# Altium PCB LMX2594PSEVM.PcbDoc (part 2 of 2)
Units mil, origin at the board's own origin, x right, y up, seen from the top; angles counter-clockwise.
Board outline 1260 x 3135 mil, 4 copper layers (Top Layer, GND, Power, Bottom Layer), stack 61.6 mil thick; 123 components, 80 nets, 426 pads, 190 vias.
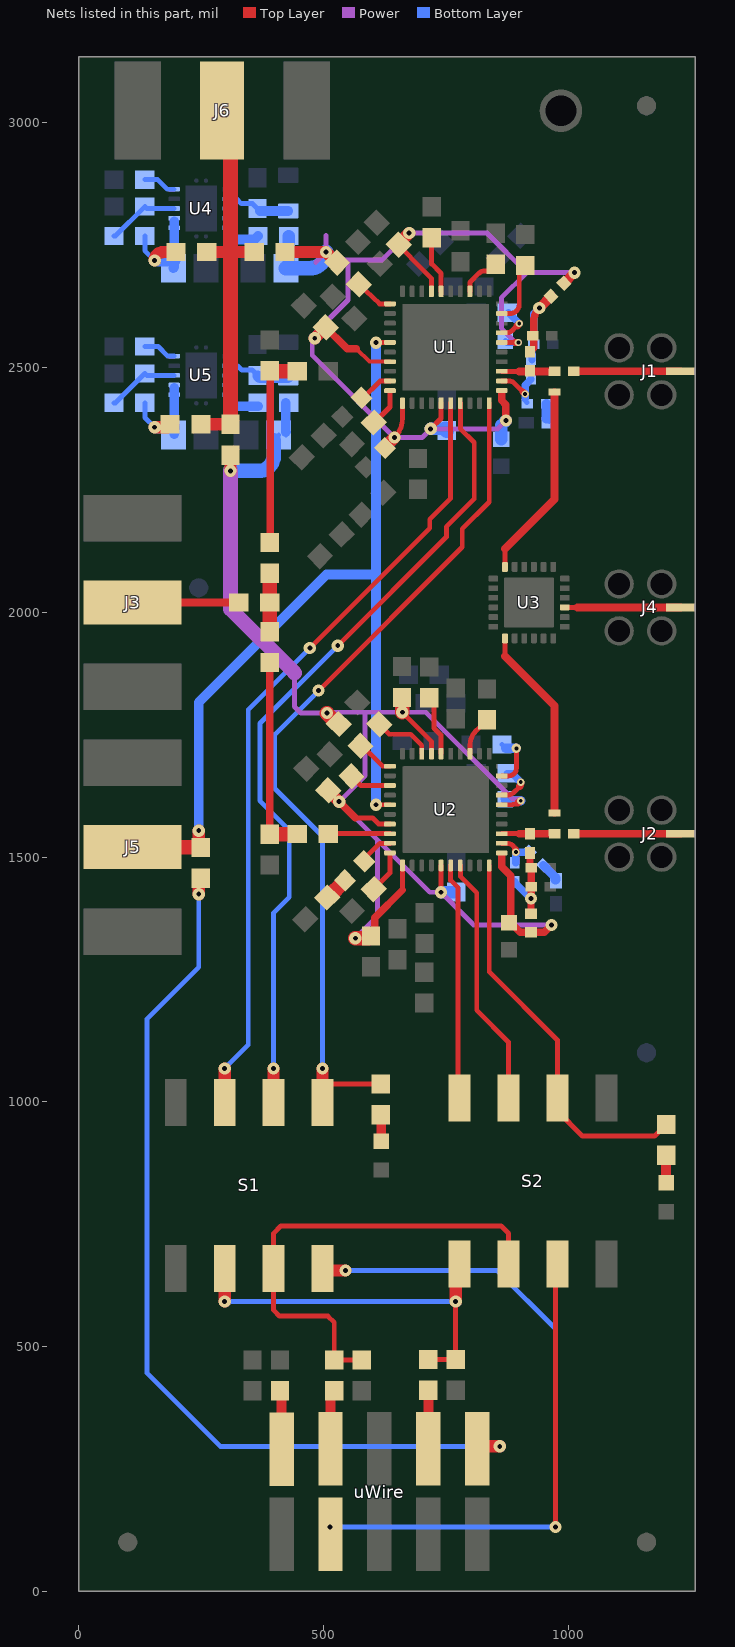
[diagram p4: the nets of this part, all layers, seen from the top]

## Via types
v1: diameter 25, hole 10, Top Layer to Bottom Layer, tented both sides, 120 vias
v2: diameter 19.68, hole 7.87, Top Layer to Bottom Layer, tented bottom, 29 vias
v3: diameter 28, hole 16, Top Layer to Bottom Layer, tented both sides, 18 vias
v4: diameter 15, hole 8, Top Layer to Bottom Layer, tented both sides, 14 vias
v5: diameter 19.68, hole 7.87, Top Layer to Bottom Layer, tented top, 8 vias
v6: diameter 20, hole 8, Top Layer to Bottom Layer, tented both sides, 1 vias

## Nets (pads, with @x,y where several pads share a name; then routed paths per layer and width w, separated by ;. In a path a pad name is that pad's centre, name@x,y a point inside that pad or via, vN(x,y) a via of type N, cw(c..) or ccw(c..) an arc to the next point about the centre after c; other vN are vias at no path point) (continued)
NetC10_2: C10.2 U1.9 | length 71.8
  Top Layer w10: C10.2@579.15,2436.17 615.64,2472.67 U1.9@635.86,2472.67
NetC11_2: C11.2 U1.10 | length 86.3
  Top Layer w10: C11.2@598.14,2381.86 635.86,2419.57 U1.10@635.86,2452.57
NetC13_1: C13.1 C13p.1 R21.2 U1.23 | length 103.6
  Top Layer w10: U1.23@864.17,2492.35 899.81,2492.35
  Top Layer w16: 900,2492.34 C13.1@968,2492.34
NetC13_2: C13.2 J1.1 | length 218.3
  Top Layer w16: C13.2@1011.69,2492.36 J1.1@1230,2492.36
NetC14_2: C14.2 C15.2 L1.1 R21.1 R22.2 | length 242.8
  Top Layer w15: R21.1@922,2532.54 929.31,2539.86 929.31,2562 929.31,2593.79 cw(c969.21,2593.79) v1(941,2622)
  Top Layer w20: v1(941,2622) L1.1@964.78,2645.78
  Bottom Layer w10: C15.2@924,2539.69 C15.2@929.31,2545
  Bottom Layer w15: R22.2@926,2515.79 C15.2@926,2540 ; C15.2@929.31,2545 929.31,2610.31 v1(941,2622)
NetC16_1: C16.1 U1.29 | length 131.2
  Top Layer w10: U1.29@864.17,2610.47 881.47,2610.47 ccw(c881.47,2629) 900,2629 900,2696.71 C16.1@912.05,2708.76
NetC17_1: C17.1 U1.33 | length 114.9
  Top Layer w10: U1.33@799.21,2655.74 799.21,2674.21 818.46,2693.46 cw(c827,2684.93) 827,2697 C17.1@837.64,2697 ; C17.1@837.64,2697 852,2697 C17.1@852,2711.36 C17.1@837.64,2697
NetC18_1: C18.1 U1.36 | length 117.6
  Top Layer w10: C18.1@721,2765.36 721,2712 740.16,2692.84 U1.36@740.16,2655.74
NetC20_1: C20.1 U2.38 | length 119.2
  Top Layer w10: C20.1@615.76,1769.17 634.07,1750.86 678.14,1750.86 700.79,1728.21 U2.38@700.79,1711.03
NetC21_2: C21.2 U2.3 | length 86.5
  Top Layer w10: C21.2@557.27,1665.17 576.37,1646.07 U2.3@635.83,1646.07
NetC23_2: C23.2 U2.8 | length 126.6
  Top Layer w10: C23.2@509.5,1547 510.14,1547.65 U2.8@635.83,1547.65
NetC24_1: C24.1 R16.2 | length 51.3
  Top Layer w10: R16.2@507.27,1417.27 R16.2@509.14,1417.27
  Top Layer w30: R16.2@509.14,1417.27 C24.1@544.12,1452.25
NetC24_2: C24.2 U2.9 | length 80.9
  Top Layer w10: C24.2@583.09,1491.22 583.09,1496.09 614.96,1527.96 U2.9@635.83,1527.96 635.72,1527.86 U2.9@625.73,1527.86
NetC25_2: C25.2 U2.10 | length 86.9
  Top Layer w10: C25.2@602.68,1434.34 635.83,1467.48 U2.10@635.83,1507.48
NetC28_2: C28.2 C29.2 L2.1 R17.1 R24.2 | length 178
  Top Layer w10: C29.2@922,1479.31 C29.2@924.31,1477
  Top Layer w15: C29.2@922,1479.31 R17.1@922,1508.17 ; L2.1@924,1383.7 v1(924,1415) ; v1@924.31,1410.31 924.31,1440 C29.2@924.31,1477
  Bottom Layer w15: R24.2@891,1449.24 891,1448 v1(924,1415)
NetC30_1: C30.1 J2.1 | length 218.3
  Top Layer w16: C30.1@1011.68,1547.65 J2.1@1230,1547.65
NetC30_2: C30.2 C30p.2 R17.2 U2.23 | length 99.9
  Top Layer w10: U2.23@864.17,1547.65 896.1,1547.65
  Top Layer w16: 900,1547.65 C30p.2@968,1547.65
NetC31_2: C31.2 U2.33 | length 82
  Top Layer w10: U2.33@799.21,1711.03 799.21,1728 cw(c841.98,1728) 811.74,1758.24 C31.2@834,1780.5
NetC32_2: C32.2 U2.36 | length 108.9
  Top Layer w10: C32.2@725.56,1813.86 725.56,1763.6 740.16,1749 U2.36@740.16,1711.03
NetC34_2: C34.2 U1.27 | length 82.7
  Top Layer w10: U1.27@864.17,2571.1 872.74,2571.1 ccw(c872.74,2591.26) 887,2577 v4(900,2590)
  Top Layer w15: v4@895.76,2585.76 v4(900,2590)
  Bottom Layer w10: C34.2@875.2,2612 C34.2@878,2612
  Bottom Layer w15: C34.2@878,2612 v4(900,2590)
NetC38_1: C38.1 U2.29 | length 107
  Top Layer w8: U2.29@864.17,1665.76 U2.29@864.28,1665.86
  Top Layer w10: U2.29@864.28,1665.86 878.45,1665.86 ccw(c878.45,1681.41) 894,1681.41 v6@894,1716.86
  Bottom Layer w10: C38.1@864.5,1730 C38.1@872.5,1722
  Bottom Layer w20: C38.1@872.5,1722 v6(894,1722)
NetC39_2: C39.2 U2.27 | length 84.4
  Top Layer w10: U2.27@864.17,1626.39 874.28,1626.39 ccw(c874.28,1648.63) 890,1632.9 897.98,1640.88 ; v4@903,1651.24 v4(903,1653)
  Top Layer w15: 900.7,1644.43 ccw(c885.85,1653) v4(903,1653)
  Bottom Layer w15: C39.2@875.2,1670 886,1670 v4(903,1653)
NetC42_1: C42.1 R25.1 | length 40
  Bottom Layer w18: C42.1@948.92,1483.08 R25.1@974.3,1457.7
  Bottom Layer w20: R25.1@974.3,1453.62 R25.1@974.3,1457.7
NetC42_2: C42.2 R24.1 U2.22 | length 93.9
  Top Layer w10: U2.22@864.17,1527.96 874.9,1527.96 cw(c874.9,1509.86) v4(893,1509.86)
  Top Layer w15: v4@892.38,1514.54 cw(c874.9,1509.86) v4(893,1509.86)
  Bottom Layer w15: R24.1@893,1488.37 v4(893,1509.86) 920.02,1509.86 C42.2@921.08,1510.92
NetC43_1: C43.1 R23.1 | length 37.8
  Bottom Layer w10: R23.1@955.68,2395.54 R23.1@961.23,2390
  Bottom Layer w20: R23.1@955.68,2395.54 C43.1@955.68,2425.54
NetC43_2: C43.2 R22.1 U1.22 | length 117.8
  Top Layer w10: U1.22@864.17,2472.67 878.84,2472.67 cw(c878.84,2457.01) 889.92,2468.08 v4(912,2446)
  Top Layer w15: v4@907.76,2450.24 v4(912,2446)
  Bottom Layer w10: 912,2436.62 ccw(c923.67,2436.62) C43.2@915.42,2428.37
  Bottom Layer w15: 912,2436.62 v4(912,2446) 912,2464.1 R22.1@924,2476.1
NetC44_2: C44.2 R29.2 U4.7 | length 133.1
  Bottom Layer w10: U4.7@305.12,2844.69 322.32,2844.69 332,2835 355,2835 R29.2@365,2825 R29.2@370,2820
  Bottom Layer w20: R29.2@370,2820 C44.2@428,2820
NetC45_2: C45.2 R34.2 U5.7 | length 133.9
  Bottom Layer w10: U5.7@305.12,2503.69 324.32,2503.69 333,2495 354,2495 R34.2@365,2484
  Bottom Layer w20: R34.2@365,2484 ccw(c370,2484) 370,2479 C45.2@428,2479
NetD1_1: D1.1 R12.1 | length 35.6
  Top Layer w20: D1.1@618,922.77 R12.1@618,958.36
NetD2_1: D2.1 R13.1 | length 56
  Top Layer w20: D2.1@1200,834.39 R13.1@1200,890.36
NetJ3_1: J3.1 R3.1 | length 216
  Top Layer w16: J3.1@111,2020 R3.1@327.01,2020
NetJ4_1: J4.1 U3.3 | length 235.1
  Top Layer w10: U3.3@994.8,2009.92 1018.93,2009.92
  Top Layer w16: 1019,2009.92 J4.1@1230,2009.92
NetJ6_1: J6.1 R1.1 R2.1 R37.1 R38.1 | length 908.9
  Top Layer w25: R2.1@249.5,2384 R38.1@310,2384 ; R1.1@261.5,2736 301,2736 ; 319,2736 ccw(c319,2727) 310,2727 ccw(c301,2727) 301,2736 ; R37.1@358.5,2736 310,2736 301,2736
  Top Layer w30: J6.1@293,2959.87 J6.1@293,3025 310,3025 310,2736 310,2727 R38.1@310,2384
NetR3_2: R3.2 R4.1 R5.2 | length 119
  Top Layer w30: R5.2@390,1960.5 R3.2@390,2020 R4.1@390,2079.5
NetR7_1: R7.1 uWire.2 | length 119.7
  Top Layer w20: R7.1@411,408.36 414.27,405.09 uWire.2@414.27,290.01
NetR8_2: R8.2 uWire.4 | length 122.6
  Top Layer w10: R8.2@514.27,402.63 R8.2@522,410.36
  Top Layer w20: uWire.4@514.27,291.01 R8.2@514.27,402.63
NetR10_1: R10.1 uWire.8 | length 115.1
  Top Layer w20: uWire.8@714.27,291.01 R10.1@714.27,406.09
NetR14_2: R14.2 U2.1 | length 79.8
  Top Layer w10: R14.2@574.83,1730.86 575.23,1730.86 620.64,1685.44 U2.1@635.83,1685.44
NetR18_2: R18.2 U1.1 | length 79.5
  Top Layer w10: R18.2@572.08,2670.02 614.71,2630.15 U1.1@635.86,2630.15
NetR26_2: R26.2 uWire.10 | length 1893.9
  Top Layer w10: R26.2@245,1452.5 R26.2@249,1456.5 ; uWire.10@814.27,291.01 uWire.10@819.11,295.86
  Top Layer w25: v1(245,1424) R26.2@245,1452.5 ; uWire.10@819.11,295.86 v1(860,295.86)
  Bottom Layer w10: v1@243.93,1428.79 242,1426.86 v1@245,1423.86 ; 245,1274.86 139,1168.86 139,445.86 289,295.86 v1(860,295.86) ; 245,1275 v1@245,1423.86 ; v1(245,1424) v1@245,1423.86
NetR27_1: R27.1 R28.2 U4.3 | length 149.4
  Bottom Layer w10: R27.1@72.01,2769 75,2769 R28.2@135,2829 139,2825 U4.3@194.88,2825
NetR30_1: R30.1 U4.8 U4.9 U4.10 | length 113.1
  Bottom Layer w10: 305,2777.86 305.12,2777.74 ; U4.9@305.12,2805.32 U4.8@305.12,2824
  Bottom Layer w20: 305,2777.86 ccw(c320.86,2777.86) 320.86,2762 359,2762 R30.1@366,2769 ; 305.12,2777.74 U4.10@305.12,2785.63 305.12,2799
NetR31_2: R31.2 U4.5 | length 68
  Bottom Layer w10: R31.2@135,2884 161,2884 180.63,2864.37 U4.5@194.88,2864.37
NetR32_1: R32.1 R33.2 U5.3 | length 149.4
  Bottom Layer w10: R32.1@72.01,2428 75,2428 R33.2@135,2488 139,2484 U5.3@194.88,2484
NetR35_1: R35.1 U5.8 U5.9 U5.10 | length 110.8
  Bottom Layer w10: U5.9@305.12,2464.31 U5.8@305.12,2483
  Bottom Layer w20: 305.12,2459 U5.10@305.12,2444.63 305.12,2436.74 ccw(c320.86,2436.74) 320.86,2421 R35.1@366,2421
NetR36_2: R36.2 U5.5 | length 68
  Bottom Layer w10: R36.2@135,2543 162,2543 181.63,2523.37 U5.5@194.88,2523.37
OSCIN_U1: C9.1 R4.2 R19.2 | length 407
  Top Layer w10: R19.2@391,2493.5 R19.2@392.15,2492.35
  Top Layer w16: R4.2@391,2142.5 R19.2@391,2493.5
  Top Layer w30: R19.2@392.15,2492.35 C9.1@446.5,2492.35
OSCIN_U2: C23.1 R5.1 R15.2 | length 410
  Top Layer w10: C23.1@446,1546.5 C23.1@446.5,1547
  Top Layer w16: R15.2@390,1546.5 R5.1@390,1897.5
  Top Layer w22: C23.1@445.85,1546.05 C23.1@447.44,1547.65
  Top Layer w30: R15.2@390,1546.5 C23.1@446,1546.5
READBACK: S1.4 S2.3 uWire.3 | length 1932.3
  Top Layer w10: S1.4@498,659.57 S1.4@502.57,655 ; v1@974.27,131.13 974.27,664.84 S2.3@978,668.57
  Top Layer w25: S1.4@502.57,655 v1(545,655)
  Bottom Layer w10: v1(513,130.86) 628.25,130.86 858.75,130.86 v1(974,130.86) 974,536 855,655 v1(545,655)
READBACK_U1: R12.2 S1.5 U1.20 | length 1793.8
  Top Layer w10: v1(490,1840) 783.5,2133.5 ; S1.5@496,998.15 498,1000.15 S1.5@498,998.15 498,1036.35 R12.2@617,1036.35 ; 783.5,2152 783.5,2133.5 ; U1.20@838.58,2427.39 838.58,2225.44 783.5,2170.36 783.5,2133.5
  Top Layer w25: S1.5@498,1036.35 v1(498,1068)
  Bottom Layer w10: v1(490,1840) 400,1750 400,1640 498,1542 v1(498,1068)
READBACK_U2: R13.2 S2.6 U2.20 | length 812.2
  Top Layer w10: U2.20@838.58,1482.69 838.58,1265.28 978,1125.86 S2.6@978,1007.15 978,981 1029,930 1176.65,930 R13.2@1200,953.35
RFout1: C13p.2 U3.12 | length 398.1
  Top Layer w10: U3.12@870.79,2092.8 870.79,2129.79
  Top Layer w16: 870.79,2129.79 972,2231 C13p.2@972,2449
RFout2: C30p.1 U3.19 | length 397.7
  Top Layer w10: 870.79,1910.21 U3.19@870.79,1946.74
  Top Layer w16: 870.79,1910.21 972,1809 C30p.1@972,1591
SCK: R10.2 R11.2 S1.2 S2.1 | length 794.1
  Top Layer w10: R10.2@714,473.35 R11.2@770,473.35 v1(770,592) ; S2.1@770,660.57 S2.1@778,668.57
  Top Layer w25: v1(298,592) S1.2@298,659.57 ; v1(770,592) S2.1@770,660.57
  Bottom Layer w10: v1(298,592) v1(770,592)
SCK_U1: S1.7 U1.16 | length 1621.5
  Top Layer w10: v1@472,1925.86 v1(472,1926.86) 717,2171.86 717,2189.86 759.84,2232.7 U1.16@759.84,2427.39
  Top Layer w25: S1.7@298,998.15 v1(298,1068)
  Bottom Layer w10: v1(298,1068) 346.14,1116.14 346.14,1801 v1(472,1926.86)
SCK_U2: S2.8 U2.16 | length 440.8
  Top Layer w10: U2.16@759.84,1482.69 759.84,1452.16 775,1437 S2.8@775,1048.15
SDI: R8.1 R9.2 S1.3 S2.2 | length 983.1
  Top Layer w10: S1.3@401,662.57 S1.3@398,659.57 ; R9.2@578,472.35 R8.1@522,472.35 522,549 509,562 410,562 398,574 S1.3@398,659.57 ; S2.2@878,668.57 878,731 863,746 413,746 398,731 S1.3@398,659.57
SDI_U1: S1.6 U1.17 | length 1660.6
  Top Layer w10: v1(529,1931.86) 751,2153.86 751,2174.86 808,2231.86 808,2346.86 779.53,2375.33 U1.17@779.53,2427.39
  Top Layer w25: S1.6@398,998.15 v1(398,1068)
  Bottom Layer w10: v1(398,1068) 398,1385.86 430,1417.86 430,1554.86 370,1614.86 370,1772.86 v1(529,1931.86)
SDI_U2: S2.7 U2.17 | length 527.7
  Top Layer w10: S2.7@878,1007.15 878,1121.86 813,1186.86 813,1427 779.53,1460.47 U2.17@779.53,1471.33 ; U2.17@779.53,1471.33 U2.17@779.53,1482.69 U2.17@779.53,1471.33
SYNC: J5.1 R26.1 U1.5 U2.5 | length 1915.5
  Top Layer w10: v1(607.16,1606.7) U2.5@635.83,1606.7 ; v1@607.55,2551.41 U1.5@635.86,2551.41
  Top Layer w25: R26.1@245,1520.5 v1(245,1553.86)
  Top Layer w30: J5.1@103,1519.86 R26.1@246,1520 ; R26.1@243.93,1519.35 R26.1@245,1520.42
  Bottom Layer w20: v1(245,1553.86) 245,1816.07 505.93,2077 ; 510,2077 505.93,2077 ; v1(607.16,1606.7) v1@607.16,2550.86 ; 607.16,2077 505.93,2077
  other v1: 607,2550.86
VCC1: C2.2 C5.1 C8.2 C12.2 C35.1 C36.2 C37.1 L1.2 R18.1 R30.2 R37.2 U1.7 U1.11 U1.15 U1.21 U1.26 U1.37 | length 2571.2
  Top Layer w8: 567.5,2538.36 593.82,2512.04 U1.7@635.86,2512.04
  Top Layer w10: C8.2@499.46,2577.46 C8.2@499.46,2587.09 ; R18.1@526.44,2714.56 R18.1@527.54,2714.56 ; v1@644.77,2357 v1(645,2357) ccw(c605.29,2396.71) 661.45,2396.71 ; v1@645,2357.23 v1@645,2358 ; C5.1@653.39,2751.3 653.39,2749.61 703.13,2699.87 703.13,2699.75 720.5,2682.38 U1.37@720.47,2655.74 ; 661.45,2405 661.45,2396.71 ; U1.11@661.42,2427.39 661.45,2396.71 ; v1@722.37,2374.86 v1(719,2374.86) 740.16,2396.02 U1.15@740.16,2427.39 ; U1.26@864.17,2551.41 v4(898,2551.41)
  Top Layer w15: C8.2@499.46,2587.09 548.2,2538.36 567.5,2538.36 ; U1.21@864.2,2448.86 864.2,2432.86 872.69,2424.37 v1(872.69,2391.9) ; v4@892,2551.41 v4(898,2551.41)
  Top Layer w20: L1.2@991.22,2672.22 v1(1013,2694)
  Top Layer w25: R37.2@421.5,2736 v1(505,2736) R18.1@526.44,2714.56 ; v1(482,2560) C8.2@499.46,2577.46 ; C12.2@624.64,2336.87 v1@644.77,2357 ; C5.1@653.39,2751.3 653.39,2753.39 v1(675,2775)
  Power w10: 484.14,2715 v1@505,2735.86 ; 505,2769.86 v1(505,2736) v1@505,2735.86 ; v1(872.69,2391.9) 855.64,2374.86 v1(719,2374.86) 701.14,2357 v1(645,2357) 477,2525 477,2565 550,2638 550,2720 ; v4@893,2550.86 863.43,2580.43 863.43,2642.43 915,2694 ; v1(1013,2694) 915,2694 ; v1@505,2735.86 520.86,2720 550,2720 ; 550,2720 620,2720 v1(675,2775) 834,2775 915,2694
  Bottom Layer w10: C2.2@423,2703 C2.2@428.99,2708.99 ; C35.1@871.56,2555 C35.1@875.15,2551.41
  Bottom Layer w15: C35.1@875.15,2551.41 v4(898,2551.41)
  Bottom Layer w25: C2.2@428.99,2708.99 R30.2@428.99,2769 ; v1(719,2374.86) C36.2@748.5,2374.86 ; C37.1@863,2353.56 863,2382.21 v1(872.69,2391.9)
  Bottom Layer w30: C2.2@423,2703 472,2703 ccw(c472,2736) v1(505,2736) ; C36.2@748.5,2374.86 C36.2@752,2371.36
VCC2: C4.2 C22.2 C26.2 C27.1 C33.1 C40.1 C41.2 L2.2 R14.1 R35.2 R38.2 U2.7 U2.11 U2.15 U2.21 U2.26 U2.37 | length 3248.1
  Top Layer w5: C26.2@592.5,1334 C26.2@597,1338.5 C26.2@594.5,1336 ; C27.1@882.29,1365.81 C27.1@887.79,1365.81
  Top Layer w10: R14.1@529.33,1771.67 R14.1@531.02,1771.67 ; v1(532,1613) v1@532,1613.62 ; 565.14,1579.86 600,1579.86 612.53,1567.33 U2.7@635.83,1567.33 ; C26.2@592.5,1334 C26.2@594.5,1336 ; C26.2@597,1338.5 C26.2@605,1346.5 ; v1(661,1795.86) 720.47,1736.39 U2.37@720.47,1711.03 ; 661.42,1432.42 U2.11@661.42,1482.69 ; v1(740,1428) 740.16,1428.16 U2.15@740.16,1482.69 ; U2.26@864.17,1606.7 882.96,1606.7 ccw(c882.96,1635.04) v4(903,1615)
  Top Layer w15: v1(532,1613) 565.14,1579.86 ; C26.2@605,1346.5 605,1376 661.42,1432.42 ; U2.21@864.17,1504 864.17,1480 882.29,1461.89 882.29,1365.81 901.8,1346.3 L2.2@924,1346.3 950.84,1346.3 v1(965.7,1361.16) ; v4@897.13,1610.5 ccw(c882.96,1635.04) v4(903,1615)
  Top Layer w25: v1(310,2289) R38.2@310,2321.01 ; C22.2@509.51,1635.49 v1(532,1613)
  Top Layer w30: v1(507,1794) R14.1@529.33,1771.67 ; v1(565,1334) C26.2@592.5,1334 ; v1(661,1795.86) C33.1@661,1825.26
  Power w10: 440.78,1876.08 440.78,1807.22 454,1794 v1(507,1794) 508.86,1795.86 584.93,1795.86 ; v1(565,1334) 610,1379 610,1535 ; v4@903,1618.86 886.14,1618.86 709.14,1795.86 v1(661,1795.86) 584.93,1795.86 ; v1(965.7,1361.16) 806.84,1361.16 v1(740,1428) 717,1428 610,1535 ; 584.93,1795.86 584.93,1665.93 v1(532,1613) 610,1535
  Power w30: v1(310,2289) 310,2006 440.78,1876.08
  Bottom Layer w10: C4.2@398,2351.54 C4.2@408.46,2362 ; C4.2@423,2362 C4.2@428.99,2367.99 ; C41.2@766.5,1428 C41.2@771,1423.5
  Bottom Layer w20: C4.2@423,2367.99 R35.2@423,2428 ; C40.1@871.96,1619.72 C40.1@872.82,1618.86 ; C40.1@872.82,1615 v4(903,1615)
  Bottom Layer w25: v1(740,1428) C41.2@766.5,1428
  Bottom Layer w30: v1(310,2289) 368,2289 ccw(c368,2319) 398,2319 C4.2@398,2351.54
Vin1: C1.2 R1.2 R27.2 U4.1 U4.2 | length 248.3
  Top Layer w25: v1(155,2719) cw(c172,2719) 172,2736 R1.2@198.5,2736
  Bottom Layer w10: R27.2@135,2769 135,2739 v1(155,2719) ; 194.88,2777.74 195,2777.86
  Bottom Layer w20: C1.2@193.07,2703 194.88,2704.81 194.88,2719 194.88,2777.74 U4.1@194.88,2785.63 194.88,2799
  Bottom Layer w25: v1(155,2719) C1.2@194.88,2719
Vin2: C3.2 R2.2 R32.2 U5.1 U5.2 | length 230.3
  Top Layer w10: R2.2@180.5,2378 R2.2@186.5,2384
  Top Layer w25: v1(155,2378) R2.2@180.5,2378
  Bottom Layer w10: R32.2@135,2428 135,2398 v1(155,2378) ; C3.2@193.07,2362 C3.2@194.88,2363.81 ; C3.2@193.88,2378 C3.2@194.88,2379
  Bottom Layer w20: C3.2@194.88,2363.81 194.88,2379 U5.1@194.88,2444.63 194.88,2459
  Bottom Layer w25: v1(155,2378) C3.2@193.88,2378
pads on no net: FID1.1 FID2.1 FID3.1 FID4.1 FID5.1 FID6.1 U1.18 U1.19 U1.28 U1.30 U1.32 U1.41@692.52,2484.09 U1.41@692.52,2541.57 U1.41@692.52,2599.05 U1.41@750,2484.09 U1.41@750,2541.57 U1.41@750,2599.05 U1.41@807.48,2484.09 U1.41@807.48,2541.57 U1.41@807.48,2599.05 U2.18 U2.19 U2.28 U2.30 U2.32 U2.41@692.52,1539.38 U2.41@692.52,1596.86 U2.41@692.52,1654.34 U2.41@750,1539.38 U2.41@750,1596.86 U2.41@750,1654.34 U2.41@807.48,1539.38 U2.41@807.48,1596.86 U2.41@807.48,1654.34 U3. U4.4 U5.4 uWire.1 uWire.5 uWire.7 uWire.9

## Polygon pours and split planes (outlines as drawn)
GND on GND "GND_L02_P012" (solid, remove dead copper, pour order 12): 1260,0 1260,3135 0,3135 0,0
GND on Power "GND_L03_P036" (solid, remove dead copper, pour order 36): 0,2330 550,2330 550,3135 0,3135
VCC2 on Power "VCC2_L03_P034" (solid, remove dead copper, pour order 34): 415,1320 980,1320 980,1555 640,1895 415,1895
VCC1 on Power "VCC1_L03_P032" (solid, remove dead copper, pour order 32): 1050,2890 460,2890 460,2330 955,2330 955,2655 1050,2655
GND on Top Layer "GND_L01_P030" (solid, remove dead copper, pour order 30): 1260,1385 865,1385 865,1820 815,1820 815,2480 900,2480 900,2655 1260,2655

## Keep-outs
Keep-Out Layer:
  text ".Layer_Name" at -520,-895 h60

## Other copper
Top Layer:
  text ".Layer_Name" at -520,-895 h60
Power:
  text ".Layer_Name" at -520,-895 h60
GND:
  text ".Layer_Name" at -520,-895 h60
Bottom Layer:
  rectangle net GND: 659,2451.86 841,2630.86
  rectangle net GND: 660,1505.86 841,1686.86
  pour cut-out: 350,2730
  text ".Layer_Name" at -520,-895 h60

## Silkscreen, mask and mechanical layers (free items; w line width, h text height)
Top Overlay:
  lines w5: 490,2390 510,2410 ; 904,1519 904,1458 ; 904,1571 904,1576 940,1576 940,1571 ; 905,2470 905,2465 939,2465 939,2470 ; 905,2522 905,2543 ; 908,2553 908,2584 925,2584 ; 909,1458 904,1458 ; 924,1421 904,1421 904,1458 ; 939,2522 939,2543 ; 940,1497 940,1519 ; 944,1587 944,1607 949,1607 ; 944,2450 944,2430 949,2430 ; 956,1524 956,1519 1025,1519 1025,1524 ; 956,2515 956,2520 1025,2520 1025,2515 ; 959,1421 984,1421 984,1459 ; 959,1496 984,1496 984,1459 ; 970,2548 987,2548 ; 970,2584 987,2584 987,2549 ; 979,1459 984,1459 ; 995,1607 1000,1607 1000,1577 ; 995,2430 1000,2430 1000,2455
  lines w7: 548.52,2297.48 586,2260 ; 578.37,2474.37 613,2439 ; 580.84,1529.21 609.72,1501.53 ; 642,2316 662,2336 ; 653,2347 663,2337 ; 854,1288 910,1288 910,1324 ; 854,1391 901,1391 ; 910,1325 945,1325 945,1355.69 ; 971,2682 991,2702 1021,2672 1001,2652
  text "SDI" at 409,1088.86 h25 r90
  text "SCK" at 310,1088 h25 r90
  text "SCK" at 795,1070 h25 r90
  text "SDI" at 890,1070 h25 r90
  text "CSB" at 215,1021 h25 r90
  text "RB" at 515,1010.86 h25 r90
  text "CSB" at 1092,1000.86 h25 r90
  text "RB" at 995,994.86 h25 r90
  text ".Layer_Name" at -520,-895 h60
Bottom Overlay:
  lines w5.91: 189,2417 202.78,2417 ; 189,2420 202.78,2420 ; 189,2758 202.78,2758 ; 189,2761 202.78,2761
  lines w7: 44,2260 44,2389 ; 44,2610 44,2730 ; 789,2529 809,2529 ; 830.21,2693.08 848,2693.08 ; 836,2273 890,2273 ; 836,2340 836,2380 887,2380 ; 869,1428 913,1428 913,1450 ; 869,1490 869,1510 890,1510 ; 875,2529 899,2529 ; 889,2408 897,2408 ; 893,2409 893,2452 ; 893,2453 941,2453 ; 906,2454 906,2474 ; 906,2506 906,2516 ; 911,2570.31 928,2570.31 ; 919,1542 933.14,1527.86 ; 931,1471 951,1451 ; 942,2453 942,2473 ; 942,2505 942,2526 ; 963,1499 983,1479 ; 968,2570 991,2570 991,2532 ; 977.39,2408 985.61,2408 ; 984,1478 995.7,1478
  text ".Layer_Name" at -520,-895 h60
Top Paste:
  text ".Layer_Name" at -520,-895 h60
Bottom Paste:
  text ".Layer_Name" at -520,-895 h60
Top Solder:
  lines w14: 859.17,1547.65 952,1547.65 ; 864,2492.34 899.64,2492.34 ; 870.79,1910.21 870.79,1946.74 ; 1002.8,2010.02 1067,2010.02
  lines w15: 870.79,2092.8 870.79,2129.79
  lines w16: 1024.98,2010.02 1210.98,2010
  lines w28: 870.79,1910.21 972,1809 972,1599 ; 870.79,2129.79 972,2231 972,2441 ; 905,1547.65 1260,1547.65 ; 905,2492.34 1260,2492.34 ; 1024,2009.92 1260,2009.92
  text ".Layer_Name" at -520,-895 h60
Bottom Solder:
  text ".Layer_Name" at -520,-895 h60
Drill Guide:
  text ".Layer_Name" at -520,-895 h60
M1 Board Outline:
  the board outline again, w10
  text ".Layer_Name" at -520,-895 h60
M2 Board Dimensions:
  rectangle: 2065.39,-150.93 2440.39,-25.93
  rectangle: 1940.39,-25.93 2065.39,99.07
  lines w7: 1940.39,-25.93 2940.39,-25.93 ; 2065.39,-150.93 2065.39,99.07 ; 2190.39,-150.93 2190.39,99.07 ; 2440.39,-150.93 2440.39,99.07 ; 2690.39,-150.93 2690.39,99.07 ; 1940.39,-150.93 1940.39,99.07 2940.39,99.07 2940.39,-150.93 1940.39,-150.93
  lines w10: 1940.39,-215.93 1940.39,-195.93 ; 2000.39,-225.93 1940.39,-205.93 ; 2000.39,-185.93 1940.39,-205.93 ; 2164.47,-205.93 1940.39,-205.93 ; 2716.3,-205.93 2940.39,-205.93 ; 2880.39,-225.93 2940.39,-205.93 ; 2880.39,-185.93 2940.39,-205.93 ; 2940.39,-215.93 2940.39,-195.93
  text "1000 (mil)" at 2174.47,-241.92 h60
  text ".Layer_Name" at -520,-895 h60
M3 3D STEP Top:
  text ".Layer_Name" at -503,-895 h60
M4 3D STEP Bottom:
  text ".Layer_Name" at -546,-895 h60
M5 Assembly Top:
  lines w10: -1390.11,-964.6 5209.89,-964.6 ; -1390.11,-761.27 5211.89,-761.27 ; -1390.11,-557.93 -1390.11,-1167.93 2614.89,-1167.93 5211.89,-1167.93 5211.89,-557.93 -1389.61,-557.93 -1389.61,-1167.93 185.89,-1167.93 ; 1074.89,-1167.93 1074.89,-557.93 ; 2341.89,-761.27 2341.89,-557.93 ; 3181.89,-761.27 3181.89,-557.93 ; 3803.89,-1174.43 3803.89,-971.6
  text "COMPONENTS MARKED 'DNP' SHOULD NOT BE POPULATED." at 72.39,-375.93 h50
  text "ASSEMBLY VARIANT:" at 71.89,-491.43 h50
  text ".VariantName" at 1107.89,-491.43 h50
  text "PCB VIEWED FROM TOP SIDE" at -1326.61,-690.1 h60
  text "BOARD #:" at 1149.89,-690.1 h60
  text "REV:" at 2539.89,-690.1 h60
  text ".PCB_Rev" at 2831.39,-690.1 h60
  text "SVN REV:" at 3377.89,-690.1 h60
  text ".VersionControl_RevNumber" at 3883.89,-690.1 h60
  text "TID #:" at 1149.89,-893.43 h60
  text ".TID" at 1695.39,-893.43 h60
  text "LAYER NAME = Assembly Top" at -1298.61,-900.1 h60
  text "PLOT NAME =" at -1326.61,-1098.77 h60
  text "GENERATED    :" at 1151.89,-1098.77 h60
  text ".Print_Date" at 2021.39,-1098.77 h60
  text ".Print_Time" at 2750.39,-1098.77 h60
M6 Assembly Bottom:
  lines w10: -1392.61,-760.77 5209.39,-760.77 ; -1390.61,-964.1 5209.39,-964.1 ; 15.39,-1173.93 15.39,-971.1 ; 637.39,-760.77 637.39,-557.43 ; 1477.39,-760.77 1477.39,-557.43 ; 2744.39,-1167.43 2744.39,-557.43 ; 3633.39,-1167.43 5208.89,-1167.43 5208.89,-557.43 -1392.61,-557.43 -1392.61,-1167.43 1204.39,-1167.43 5209.39,-1167.43 5209.39,-557.43
  text "COMPONENTS MARKED 'DNP' SHOULD NOT BE POPULATED." at 5051.89,-363.43 h60
  text ".VariantName" at 4007.89,-479.43 h60
  text "ASSEMBLY VARIANT:" at 5046.89,-479.43 h60
  text ".VersionControl_RevNumber" at -64.61,-689.6 h60
  text "SVN REV:" at 441.39,-689.6 h60
  text ".PCB_Rev" at 987.89,-689.6 h60
  text "REV:" at 1279.39,-689.6 h60
  text "BOARD #:" at 2669.39,-689.6 h60
  text "PCB VIEWED FROM BOTTOM SIDE" at 5145.89,-689.6 h60
  text ".TID" at 2123.89,-892.93 h60
  text "TID #:" at 2669.39,-892.93 h60
  text "LAYER NAME = Assembly Bottom" at 5171,-911 h60
  text ".Print_Time" at 1068.89,-1098.27 h60
  text ".Print_Date" at 1797.89,-1098.27 h60
  text "GENERATED    :" at 2667.39,-1098.27 h60
  text "PLOT NAME =" at 5145.89,-1098.27 h60
M9 Title Sheet:
  lines w10: -1588.5,1003.36 -1388.5,1003.36 ; -1588.5,3378.36 -1388.5,3378.36 ; -1588.5,5753.36 -1388.5,5753.36 ; 911.5,-1371.64 911.5,-1171.64 ; 911.5,7928.36 911.5,8128.36 ; 3411.5,-1371.64 3411.5,-1171.64 ; 3411.5,7928.36 3411.5,8128.36 ; 5224,-1171.64 5224,-561.64 10206.5,-561.64 ; 5911.5,-1371.64 5911.5,-1171.64 ; 5911.5,7928.36 5911.5,8128.36 ; 8411.5,-1371.64 8411.5,-1171.64 ; 8411.5,7928.36 8411.5,8128.36 ; 10206.5,-1171.64 10206.5,-561.64 ; 10206.5,-861.64 13206.5,-861.64 ; 10206.5,-261.64 13206.5,-261.64 ; 10206.5,832.86 10206.5,332.36 10206.5,38.36 ; 10207.5,332.36 13207.5,332.36 ; 10207.5,829.36 13207.5,829.36 ; 10911.5,-1371.64 10911.5,-1171.64 ; 10911.5,7928.36 10911.5,8128.36 ; 11698,1444.36 11699,1444.36 ; 11711.5,-1161.64 11711.5,-561.64 ; 13206.5,-561.64 10206.5,-561.64 ; 13206.5,38.36 10206.5,38.36 ; 13211.5,28.36 13211.5,-1171.64 ; 13211.5,3378.36 13411.5,3378.36 ; 13211.5,5753.36 13411.5,5753.36 ; 10206.5,-561.64 10206.5,38.36 ; 13211.5,-1171.64 -1388.5,-1171.64 -1388.5,7928.36 13211.5,7928.36 13211.5,-1171.64 ; -1588.5,-1371.64 13411.5,-1371.64 13411.5,8128.36 -1588.5,8128.36 -1588.5,-1371.64
  text "1" at -357.16,7998.36 h70
  text "2" at 2138.5,7998.36 h70
  text "3" at 4627.84,7998.36 h70
  text "4" at 7134.51,7998.36 h70
  text "5" at 9633.5,7998.36 h70
  text "6" at 12138.5,7998.36 h70
  text "A" at -1513.5,6855.36 h70
  text "A" at 13286.5,6855.36 h70
  text "B" at -1513.5,4475.36 h70
  text "B" at 13286.5,4475.36 h70
  text "C" at -1513.5,2100.36 h70
  text "C" at 13286.5,2100.36 h70
  text "PROJECT TITLE:" at 10246.5,239.36 h45
  text "DESIGNED FOR:" at 10246.5,-61.64 h45
  text ".PRJ_Customer" at 10296.5,-201.64 h70
  text "D" at -1513.5,-269.64 h70
  text "D" at 13286.5,-269.64 h70
  text "FILE NAME:" at 10246.5,-361.64 h45
  text "Texas Instruments (TI) and/or its licensors do not warrant the accuracy or completeness of this specification" at 5277,-643.48 h45
  text "ENGINEER:" at 10246.5,-651.64 h45
  text "LAYOUT BY:" at 11751.5,-651.64 h45
  text "or any information contained therein. TI and/or its licensors do not warrant that this design will meet" at 5232.01,-756.15 h45
  text "the specifications, will be suitable for your application or fit for any particular purpose, or will operate in" at 5232.01,-868.81 h45
  text ".Layer_Name" at -520,-895 h60
  text "ALTIUM DESIGNER VERSION:" at 11751.5,-961.64 h45
  text "an implementation. TI and/or its licensors do not warrant that the design is production worthy. You should" at 5232.01,-981.48 h45
  text "completely validate and test your design implementation to confirm the system functionality for your application." at 5277,-1094.14 h45
  text ".print_Scale" at 10296.5,-1094.97 h70
  text ".Application_BuildNumber" at 11802,-1094.97 h70
  text "1" at -357.16,-1301.64 h70
  text "2" at 2138.5,-1301.64 h70
  text "3" at 4627.84,-1301.64 h70
  text "4" at 7134.51,-1301.64 h70
  text "5" at 9633.5,-1301.64 h70
  text "6" at 12138.5,-1301.64 h70
M10 Fab Notes:
  drawing of 189 lines, arcs and shapes, not listed
  text "DESIGN INFORMATION" at 11287.25,6311.83 h60
  text "MIN. TRACK WIDTH:" at 10642.7,6179.7 h60
  text "10" at 11738.94,6179.7 h60
  text "MIL" at 11893.7,6179.7 h60
  text "7.874" at 11568.06,6060.43 h60
  text "MIN. CLEARANCE:" at 10642.7,6055.58 h60
  text "MIL" at 11893.7,6055.58 h60
  text "MIN. VIA PAD SIZE:" at 10642.7,5931.45 h60
  text "15" at 11708.95,5931.45 h60
  text "MIL" at 11893.7,5931.45 h60
  text "0.05mm (2MIL)" at 11337.7,5801.55 h60
  text "MINIMUM ANNULAR RING" at 10313.46,5793.33 h60
  text "EXTERNAL" at 12045.7,5793.33 h60
  text "PER" at 10513.46,5683.2 h60
  text "IPC-D-275 CLASS 2 LEVEL C" at 10733.46,5683.2 h60
  text "MIL, HOLES" at 12221.7,5582.72 h60
  text "+/-" at 11829.24,5574.14 h60
  text "+/-" at 12683.24,5574.14 h60
  text "REGISTRATION TOLERANCES:" at 10313.46,5573.07 h60
  text "METAL" at 11513.24,5573.07 h60
  text "5" at 12089.44,5573.08 h60
  text "3" at 12922.44,5573.08 h60
  text "MIL" at 13038.7,5573.07 h60
  text "HOLE SIZE TOLERANCE (UNLESS OTHERWISE SPECIFIED):" at 10313.46,5474.76 h60
  text "+/-" at 12683.24,5471.88 h60
  text "3" at 12922.44,5470.82 h60
  text "MIL" at 13038.7,5470.82 h60
  text "MATERIAL:" at 10238.7,5333.17 h60
  text "FR-4 High Tg" at 11225.14,5204.65 h60
  text "X" at 11970,5200 h60
  text "See table" at 12590,5200 h60
  text "FR-408" at 10659.7,5192.14 h60
  text "OTHER" at 12147.7,5192.14 h60
  text "62 MIL (1.6mm) +/-10%" at 10979.8,5049.11 h60
  text "X" at 10859.7,5046.66 h60
  text "THICKNESS:" at 10313.46,5040.89 h60
  text "OTHER" at 12264.7,5040.89 h60
  text "TOLERANCE:" at 10313.46,4902.58 h60
  text "X" at 11161.7,4902.58 h60
  text "ANSI IPC-6012 TYPE 3 CLASS 2" at 11339.71,4902.58 h60
  text "OTHER +/-" at 11339.7,4758.39 h60
  text "BOW & TWIST:" at 10313.46,4613.2 h60
  text "X" at 11161.7,4613.2 h60
  text "ANSI IPC-6012 TYPE 3 CLASS 2" at 11339.71,4613.2 h60
  text "OTHER +/-" at 11339.7,4466.5 h60
  text "DRILLING:" at 10238.7,4335.88 h60
  text "NC_DRILL FILES" at 11999.7,4230.69 h60
  text "REFERENCE:" at 10313.46,4226.76 h60
  text "X" at 10970.7,4226.66 h60
  text "AS SHOWN" at 11148.7,4226.76 h60
  text "X" at 11871.7,4226.76 h60
  text "OTHER" at 12297.7,4084.5 h60
  text "PTH COPPER THICKNESS:" at 10313.14,4080.98 h60
  text "X" at 11452.38,4080.98 h60
  text "20-30 um" at 11580.37,4080.98 h60
  text "BOARD FINISH:" at 10238.7,3933.38 h60
  text "SILKSCREEN:" at 10393.92,3823.25 h60
  text "X" at 11351.7,3823.25 h60
  text "TOP" at 11468.7,3823.25 h60
  text "X" at 11861.7,3823.25 h60
  text "BOTTOM" at 11979.7,3823.25 h60
  text "BLACK" at 12540,3680 h60
  text "SILKSCREEN COLOR:" at 10393.92,3668.06 h60
  text "WHITE" at 11468.7,3668.06 h60
  text "OTHER" at 11979.7,3668.06 h60
  text "X" at 11860,3660 h60
  text "X" at 12070,3530 h60
  text "WHITE" at 12570,3530 h60
  text "GREEN" at 11599.7,3524.62 h60
  text "OTHER" at 12217.7,3524.62 h60
  text "SOLDER RESIST COLOR:" at 10393.92,3517.75 h60
  text "X" at 11481.7,3370.36 h60
  text "MATTE" at 11599.7,3370.36 h60
  text "SEMI-GLOSS" at 12217.24,3369.73 h60
  text "IMMERSION GOLD (ENIG)" at 11299.7,3197.59 h60
  text "ENEPIG" at 12637.24,3190.37 h60
  text "SURFACE FINISH:" at 10238.7,3189.37 h60
  text "X" at 11121.7,3189.37 h60
  text "IMM. TIN/SILVER OR EQUIV" at 10568.24,3052.06 h60
  text "OTHER" at 11999.7,3048.12 h60
  text "ARRAY/PANEL:" at 10238.7,2892.74 h60
  text "CUT AND TRIM PER M1 BOARD OUTLINE" at 11299.7,2884.52 h60
  text "N.C. ROUTE" at 11299.7,2748.55 h60
  text "X" at 11987.7,2748.55 h60
  text "V. SCORE" at 12165.7,2748.55 h60
  text "CERTIFICATION:" at 10238.7,2619.43 h60
  text "MATERIALS AND WORKMANSHIP FOR ALL PCBS" at 10963.7,2619.43 h60
  text "TO MEET OR EXCEED THE REQUIREMENTS OF:" at 10963.7,2525.36 h60
  text "X" at 10601.2,2396.73 h60
  text "ANSI IPC-A-600F CLASS ->" at 10729.2,2396.73 h60
  text "X" at 12377.2,2396.73 h60
  text "2" at 12487.2,2396.73 h60
  text "1" at 12172.2,2395.24 h60
  text "3" at 12841.2,2395.24 h60
  text "X" at 11413.2,2249.05 h60
  text "RoHS" at 11541.2,2249.05 h60
  text "OTHER" at 12185.6,2249.05 h60
  text "PER ORDER" at 12582.66,2249.05 h60
  text "ALL BOARDS MUST MEET OR EXCEED UL94-V0 REQUIREMENTS." at 10266.24,2095.22 h60
  text "PCB MUST BEAR THE UL94V-0 UL REGISTERED MATERIAL ID NUMBER" at 10266.24,1979.16 h60
  text "ADDITIONAL REQUIREMENTS:" at 10238.7,1809.73 h60
  text "MICROSECTION:" at 10313.46,1702.61 h60
  text "YES" at 11219.2,1702.61 h60
  text "REQUIRED" at 12080.7,1558.27 h60
  text "BARE BOARD ELEC. TEST:" at 10313.46,1555.42 h60
  text "NONE" at 11619.2,1555.42 h60
  text "X" at 11962.7,1555.42 h60
  text "PER ORDER" at 12672.7,1555.42 h60
  text "XX MIL VIAS REQUIRE NON-CONDUCTIVE FILL AND PLANARIZE" at 10481.61,1350.47 h59
  text "XX MIL VIAS REQUIRE CONDUCTIVE FILL AND PLANARIZE" at 10489.61,1246.5 h60
  text "OUTER XX MIL TRACES REQUIRE 50 OHM SINGLE-ENDED IMPEDANCE" at 10488.63,1083.11 h58
  text "LAYER 2 & 3 (INNER LAYERS) XX MIL WIDE, XX MIL SPACE / TRACES REQUIRE 100 OHM DIFFERENTIAL IMPEDANCE" at 10480.63,847.4 h60
  text ".Layer_Name" at -520,-895 h60
M11 Gerber Information:
  lines w10: -1390.11,-962.6 5209.89,-962.6 ; -1390.11,-759.27 5211.89,-759.27 ; -1390.11,-555.93 -1390.11,-1165.93 2614.89,-1165.93 5211.89,-1165.93 5211.89,-555.93 -1389.61,-555.93 -1389.61,-1165.93 185.89,-1165.93 ; 1074.89,-1165.93 1074.89,-555.93 ; 2341.89,-759.27 2341.89,-555.93 ; 3181.89,-759.27 3181.89,-555.93 ; 3803.89,-1172.43 3803.89,-969.6
  text "ALL ARTWORK VIEWED FROM TOP SIDE" at -1326.61,-688.1 h60
  text "BOARD #:" at 1149.89,-688.1 h60
  text "REV:" at 2539.89,-688.1 h60
  text ".PCB_Rev" at 2831.39,-688.1 h60
  text "SVN REV:" at 3377.89,-688.1 h60
  text ".VersionControl_RevNumber" at 3883.89,-688.1 h60
  text "TID #:" at 1149.89,-891.43 h60
  text ".TID" at 1695.39,-891.43 h60
  text "LAYER NAME =" at -1328,-896 h60
  text "PLOT NAME =" at -1326.61,-1096.77 h60
  text "GENERATED    :" at 1151.89,-1096.77 h60
  text ".Print_Date" at 2021.39,-1096.77 h60
  text ".Print_Time" at 2750.39,-1096.77 h60
M12 Stackup:
  drawing of 295 lines, arcs and shapes, not listed
  text "Layer" at 2047.5,2007.5 h60
  text "Name" at 2457.41,2007.5 h60
  text "Material" at 3387.16,2007.5 h60
  text "Thickness" at 4246.92,2007.5 h60
  text "Constant" at 4896.76,2007.5 h60
  text "Board Layer Stack" at 5466.62,2007.5 h60
  text "1" at 2047.5,1887.5 h60
  text "Top Overlay" at 2457.41,1887.5 h60
  text "2" at 2047.5,1767.5 h60
  text "Top Solder" at 2457.41,1767.5 h60
  text "Solder Resist" at 3387.16,1767.5 h60
  text "0.40mil" at 4246.92,1767.5 h60
  text "3.5" at 4896.76,1767.5 h60
  text "3" at 2047.5,1647.5 h60
  text "Top Layer" at 2457.41,1647.5 h60
  text "Copper" at 3387.16,1647.5 h60
  text "1.40mil" at 4246.92,1647.5 h60
  text "4" at 2047.5,1527.5 h60
  text "Dielectric 1" at 2457.41,1527.5 h60
  text "RO4350B" at 3387.16,1527.5 h60
  text "8.00mil" at 4246.92,1527.5 h60
  text "3.66" at 4896.76,1527.5 h60
  text "5" at 2047.5,1407.5 h60
  text "GND" at 2457.41,1407.5 h60
  text "Copper" at 3387.16,1407.5 h60
  text "1.40mil" at 4246.92,1407.5 h60
  text "6" at 2047.5,1287.5 h60
  text "Dielectric 2" at 2457.41,1287.5 h60
  text "FR-4 High Tg" at 3387.16,1287.5 h60
  text "40.00mil" at 4246.92,1287.5 h60
  text "4.2" at 4896.76,1287.5 h60
  text "7" at 2047.5,1167.5 h60
  text "Power" at 2457.41,1167.5 h60
  text "Copper" at 3387.16,1167.5 h60
  text "1.40mil" at 4246.92,1167.5 h60
  text "8" at 2047.5,1047.5 h60
  text "Dielectric 3" at 2457.41,1047.5 h60
  text "FR-4 High Tg" at 3387.16,1047.5 h60
  text "8.00mil" at 4246.92,1047.5 h60
  text "4.2" at 4896.76,1047.5 h60
  text "9" at 2047.5,927.5 h60
  text "Bottom Layer" at 2457.41,927.5 h60
  text "Copper" at 3387.16,927.5 h60
  text "1.40mil" at 4246.92,927.5 h60
  text "10" at 2047.5,807.5 h60
  text "Bottom Solder" at 2457.41,807.5 h60
  text "Solder Resist" at 3387.16,807.5 h60
  text "0.40mil" at 4246.92,807.5 h60
  text "3.5" at 4896.76,807.5 h60
  text "11" at 2047.5,687.5 h60
  text "Bottom Overlay" at 2457.41,687.5 h60
  text ".Layer_Name" at -520,-895 h60
M13 Component Bodies Top:
  text ".Layer_Name" at -554,-878 h60
M14 Component Bodies Bottom:
  text ".Layer_Name" at -563,-895 h60
M15 Courtyards Top:
  text ".Layer_Name" at -511,-869 h60
M16 Courtyards Bottom:
  text ".Layer_Name" at -520,-869 h60
Drill Drawing:
  lines w10: 2036.09,2362.06 2063.72,2375.87 2091.34,2362.06 2077.53,2389.68 2091.34,2417.31 2063.72,2403.5 2036.09,2417.31 2049.9,2389.68 2036.09,2362.06 ; 2036.09,2486.38 2091.34,2486.38 2091.34,2541.63 2036.09,2541.63 2036.09,2486.38 ; 2036.09,2610.7 2036.09,2624.51 2049.9,2638.32 2036.09,2652.14 2036.09,2665.95 2049.9,2665.95 2063.72,2652.14 2077.53,2665.95 2091.34,2665.95 2091.34,2652.14 2077.53,2638.32 2091.34,2624.51 2091.34,2610.7 2077.53,2610.7 2063.72,2624.51 2049.9,2610.7 2036.09,2610.7 ; 2036.09,2762.64 2063.72,2735.02 2091.34,2762.64 2063.72,2790.27 2036.09,2762.64 ; 2036.09,2873.15 2049.9,2873.15 2049.9,2859.34 2077.53,2859.34 2077.53,2873.15 2091.34,2873.15 2091.34,2900.78 2077.53,2900.78 2077.53,2914.59 2049.9,2914.59 2049.9,2900.78 2036.09,2900.78 2036.09,2873.15 ; 2036.09,2983.66 2091.34,2983.66 2091.34,3038.91 2036.09,3038.91 2036.09,2983.66 ; 2047.14,2994.71 2080.29,2994.71 2080.29,3027.86 2047.14,3027.86 2047.14,2994.71
  lines w12: 1986,2324.76 5217.49,2324.76 ; 1986,3070.68 5217.49,3070.68 ; 2323.86,2200.44 2323.86,3195 ; 2655.86,2200.44 2655.86,3195 ; 3292.43,2200.44 3292.43,3195 ; 3551.57,2200.44 3551.57,3195 ; 3926.72,2200.44 3926.72,3195 ; 4651.05,2200.44 4651.05,3195 ; 1986,2200.44 5217.49,2200.44 5217.49,3195 1986,3195 1986,2200.44
  text "Symbol" at 2060.59,3107.98 h72
  text "Quantity" at 2361.16,3107.98 h72
  text "Finished Hole Size" at 2693.16,3107.98 h72
  text "Plated" at 3329.72,3107.98 h72
  text "Hole Type" at 3588.86,3107.98 h72
  text "Drill Layer Pair" at 3964.02,3107.98 h72
  text "Hole Tolerance" at 4688.35,3107.98 h72
  text "37" at 2361.16,2983.66 h60
  text "7.87mil (0.200mm)" at 2693.16,2983.66 h60
  text "PTH" at 3329.72,2983.66 h60
  text "Round" at 3588.86,2983.66 h60
  text "Top Layer - Bottom Layer" at 3964.02,2983.66 h60
  text "15" at 2361.16,2859.34 h60
  text "8.00mil (0.203mm)" at 2693.16,2859.34 h60
  text "PTH" at 3329.72,2859.34 h60
  text "Round" at 3588.86,2859.34 h60
  text "Top Layer - Bottom Layer" at 3964.02,2859.34 h60
  text "120" at 2361.16,2735.02 h60
  text "10.00mil (0.254mm)" at 2693.16,2735.02 h60
  text "PTH" at 3329.72,2735.02 h60
  text "Round" at 3588.86,2735.02 h60
  text "Top Layer - Bottom Layer" at 3964.02,2735.02 h60
  text "18" at 2361.16,2610.7 h60
  text "16.00mil (0.406mm)" at 2693.16,2610.7 h60
  text "PTH" at 3329.72,2610.7 h60
  text "Round" at 3588.86,2610.7 h60
  text "Top Layer - Bottom Layer" at 3964.02,2610.7 h60
  text "12" at 2361.16,2486.38 h60
  text "45.00mil (1.143mm)" at 2693.16,2486.38 h60
  text "PTH" at 3329.72,2486.38 h60
  text "Round" at 3588.86,2486.38 h60
  text "Top Layer - Bottom Layer" at 3964.02,2486.38 h60
  text "1" at 2361.16,2362.06 h60
  text "63.00mil (1.600mm)" at 2693.16,2362.06 h60
  text "PTH" at 3329.72,2362.06 h60
  text "Round" at 3588.86,2362.06 h60
  text "Top Layer - Bottom Layer" at 3964.02,2362.06 h60
  text "203 Total" at 2361.16,2237.74 h60
  text ".Layer_Name" at -520,-895 h60

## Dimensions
1260,-50 to 0,-50 on M2 Board Dimensions
1310,0 to 1310,3135 on M2 Board Dimensions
